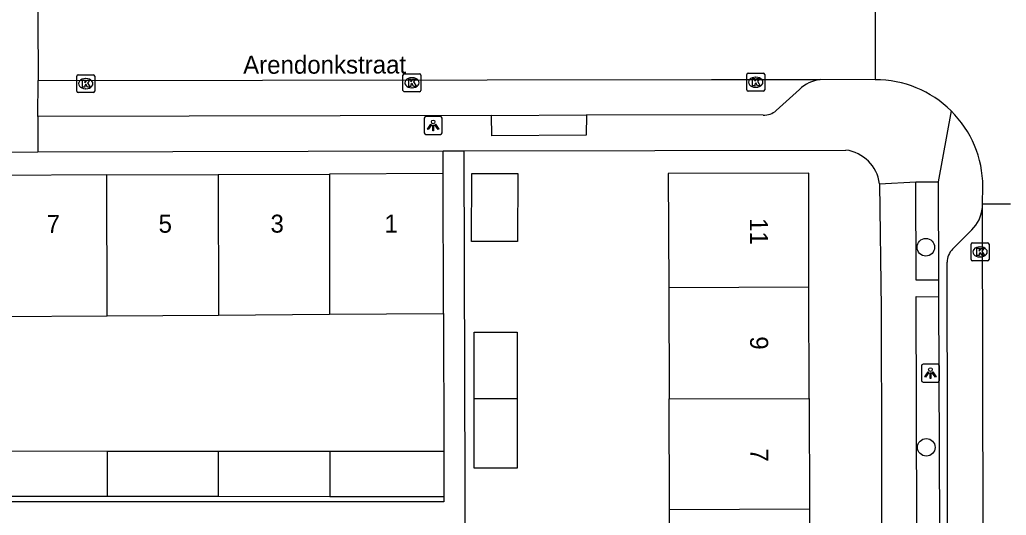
# Model space of a CAD drawing. Extents: x 160732 to 162105, y 387428 to 388479.
# Drawn here: x 161247.5 to 161302.4, y 387840.8 to 387868.4 of the extents above; entities that cross this region are included whole.
import ezdxf

# ---------------------------------------------------------------- set-up
doc = ezdxf.new("R2010")
doc.units = 0
for name, color, linetype in [('IMGEO_Boom', 7, 'Continuous'), ('IMGEO_Kolk', 7, 'Continuous'), ('IMGEO_Lichtpunt', 7, 'Continuous'), ('IMGEO_Openbare_ruimte_label', 7, 'Continuous'), ('IMGEO_Pand', 7, 'Continuous'), ('IMGEO_Pand_nummerreeks', 7, 'Continuous'), ('IMGEO_Rijbaan_lokaal_gesloten', 7, 'Continuous'), ('IMGEO_Rijbaan_lokaal_open', 7, 'Continuous'), ('IMGEO_Voetpad_open', 7, 'Continuous')]:
    doc.layers.add(name, color=color, linetype=linetype)

msp = doc.modelspace()

# ---------------------------------------------------------------- linework, layer by layer
at = {"layer": 'IMGEO_Boom'}
for centre in [(161297.937, 387855.714), (161297.961, 387844.569)]:
    msp.add_circle(centre, 0.489, dxfattribs=at)
at = {"layer": 'IMGEO_Kolk'}
for p, q in [((161250.701, 387864.399), (161250.701, 387865.251)), ((161250.776, 387865.325), (161251.628, 387865.325)), ((161251.702, 387865.251), (161251.702, 387864.399)), ((161268.851, 387864.45), (161268.851, 387865.302)), ((161268.926, 387865.376), (161269.778, 387865.376)), ((161269.852, 387865.302), (161269.852, 387864.45)), ((161287.973, 387864.48), (161287.973, 387865.332)), ((161288.048, 387865.406), (161288.9, 387865.406)), ((161288.974, 387865.332), (161288.974, 387864.48)), ((161251.189, 387865.105), (161251.214, 387865.105)), ((161269.339, 387865.156), (161269.364, 387865.156)), ((161288.461, 387865.186), (161288.486, 387865.186)), ((161251.628, 387864.325), (161250.776, 387864.325)), ((161251.212, 387864.545), (161251.187, 387864.545)), ((161269.778, 387864.376), (161268.926, 387864.376)), ((161269.362, 387864.596), (161269.337, 387864.596)), ((161288.9, 387864.406), (161288.048, 387864.406)), ((161288.484, 387864.626), (161288.459, 387864.626)), ((161300.527, 387855.954), (161301.379, 387855.954)), ((161300.452, 387855.028), (161300.452, 387855.88)), ((161300.94, 387855.734), (161300.965, 387855.734)), ((161301.453, 387855.88), (161301.453, 387855.028)), ((161301.379, 387854.954), (161300.527, 387854.954)), ((161300.963, 387855.174), (161300.938, 387855.174))]:
    msp.add_line(p, q, dxfattribs=at)
for points in [[(161250.701, 387864.399), (161250.701, 387865.251)], [(161250.776, 387865.325), (161251.628, 387865.325)], [(161251.702, 387865.251), (161251.702, 387864.399)], [(161268.851, 387864.45), (161268.851, 387865.302)], [(161268.926, 387865.376), (161269.778, 387865.376)], [(161269.852, 387865.302), (161269.852, 387864.45)], [(161287.973, 387864.48), (161287.973, 387865.332)], [(161288.048, 387865.406), (161288.9, 387865.406)], [(161288.974, 387865.332), (161288.974, 387864.48)], [(161251.022, 387865.025), (161251.145, 387865.025), (161251.145, 387864.874), (161251.275, 387865.025), (161251.439, 387865.025), (161251.293, 387864.874), (161251.446, 387864.625), (161251.294, 387864.625), (161251.209, 387864.789), (161251.145, 387864.722), (161251.145, 387864.625), (161251.022, 387864.625), (161251.022, 387865.025)], [(161269.172, 387865.076), (161269.295, 387865.076), (161269.295, 387864.925), (161269.425, 387865.076), (161269.589, 387865.076), (161269.443, 387864.925), (161269.596, 387864.676), (161269.444, 387864.676), (161269.359, 387864.84), (161269.295, 387864.773), (161269.295, 387864.676), (161269.172, 387864.676), (161269.172, 387865.076)], [(161288.294, 387865.106), (161288.417, 387865.106), (161288.417, 387864.955), (161288.547, 387865.106), (161288.711, 387865.106), (161288.565, 387864.955), (161288.718, 387864.706), (161288.566, 387864.706), (161288.481, 387864.87), (161288.417, 387864.803), (161288.417, 387864.706), (161288.294, 387864.706), (161288.294, 387865.106)], [(161251.628, 387864.325), (161250.776, 387864.325)], [(161269.778, 387864.376), (161268.926, 387864.376)], [(161288.9, 387864.406), (161288.048, 387864.406)], [(161300.527, 387855.954), (161301.379, 387855.954)], [(161300.452, 387855.028), (161300.452, 387855.88)], [(161300.773, 387855.654), (161300.896, 387855.654), (161300.896, 387855.503), (161301.026, 387855.654), (161301.19, 387855.654), (161301.044, 387855.503), (161301.197, 387855.254), (161301.045, 387855.254), (161300.96, 387855.418), (161300.896, 387855.351), (161300.896, 387855.254), (161300.773, 387855.254), (161300.773, 387855.654)], [(161301.453, 387855.88), (161301.453, 387855.028)], [(161301.379, 387854.954), (161300.527, 387854.954)]]:
    msp.add_lwpolyline(points, dxfattribs=at)
for centre, start, end in [((161250.778, 387865.249), 91.552, 178.448), ((161250.778, 387865.249), 91.552, 178.448), ((161251.626, 387865.249), 1.552, 88.448), ((161251.626, 387865.249), 1.552, 88.448), ((161268.928, 387865.3), 91.552, 178.448), ((161268.928, 387865.3), 91.552, 178.448), ((161269.776, 387865.3), 1.552, 88.448), ((161269.776, 387865.3), 1.552, 88.448), ((161288.05, 387865.33), 91.552, 178.448), ((161288.05, 387865.33), 91.552, 178.448), ((161288.898, 387865.33), 1.552, 88.448), ((161288.898, 387865.33), 1.552, 88.448), ((161250.778, 387864.401), 181.552, 268.448), ((161250.778, 387864.401), 181.552, 268.448), ((161251.626, 387864.401), 271.552, 358.448), ((161251.626, 387864.401), 271.552, 358.448), ((161268.928, 387864.452), 181.552, 268.448), ((161268.928, 387864.452), 181.552, 268.448), ((161269.776, 387864.452), 271.552, 358.448), ((161269.776, 387864.452), 271.552, 358.448), ((161288.05, 387864.482), 181.552, 268.448), ((161288.05, 387864.482), 181.552, 268.448), ((161288.898, 387864.482), 271.552, 358.448), ((161288.898, 387864.482), 271.552, 358.448), ((161300.529, 387855.878), 91.552, 178.448), ((161300.529, 387855.878), 91.552, 178.448), ((161301.377, 387855.878), 1.552, 88.448), ((161301.377, 387855.878), 1.552, 88.448), ((161300.529, 387855.03), 181.552, 268.448), ((161300.529, 387855.03), 181.552, 268.448), ((161301.377, 387855.03), 271.552, 358.448), ((161301.377, 387855.03), 271.552, 358.448)]:
    msp.add_arc(centre, 0.0765, start, end, dxfattribs=at)
for centre, major_axis, ratio, start_param, end_param in [((161251.188, 387864.825), (-0.387, 0.002), 0.722429, 4.712389, 7.853982), ((161251.213, 387864.825), (-0.39, 0.002), 0.717154, 1.570796, 4.712389), ((161269.338, 387864.876), (-0.387, 0.002), 0.722429, 4.712389, 7.853982), ((161269.363, 387864.876), (-0.39, 0.002), 0.717154, 1.570796, 4.712389), ((161288.46, 387864.906), (-0.387, 0.002), 0.722429, 4.712389, 7.853982), ((161288.485, 387864.906), (-0.39, 0.002), 0.717154, 1.570796, 4.712389), ((161300.939, 387855.454), (-0.387, 0.002), 0.722429, 4.712389, 7.853982), ((161300.964, 387855.454), (-0.39, 0.002), 0.717154, 1.570796, 4.712389)]:
    msp.add_ellipse(centre, major_axis=major_axis, ratio=ratio, start_param=start_param, end_param=end_param, dxfattribs=at)
at = {"layer": 'IMGEO_Lichtpunt'}
for p, q in [((161270.034, 387862.898), (161270.034, 387862.091)), ((161270.034, 387862.898), (161270.034, 387862.091)), ((161270.936, 387862.993), (161270.128, 387862.993)), ((161270.936, 387862.993), (161270.128, 387862.993)), ((161271.03, 387862.091), (161271.03, 387862.898)), ((161271.03, 387862.091), (161271.03, 387862.898)), ((161270.128, 387861.997), (161270.936, 387861.997)), ((161270.128, 387861.997), (161270.936, 387861.997)), ((161297.694, 387849.103), (161297.694, 387848.296)), ((161297.694, 387849.103), (161297.694, 387848.296)), ((161298.596, 387849.198), (161297.788, 387849.198)), ((161298.596, 387849.198), (161297.788, 387849.198)), ((161298.69, 387848.296), (161298.69, 387849.103)), ((161298.69, 387848.296), (161298.69, 387849.103)), ((161297.788, 387848.202), (161298.596, 387848.202)), ((161297.788, 387848.202), (161298.596, 387848.202))]:
    msp.add_line(p, q, dxfattribs=at)
for points in [[(161270.408, 387862.562), (161270.447, 387862.534), (161270.259, 387862.272), (161270.221, 387862.299), (161270.408, 387862.562)], [(161270.51, 387862.514), (161270.557, 387862.514), (161270.557, 387862.192), (161270.51, 387862.192), (161270.51, 387862.514)], [(161270.62, 387862.534), (161270.658, 387862.561), (161270.845, 387862.299), (161270.806, 387862.271), (161270.62, 387862.534)], [(161298.068, 387848.767), (161298.107, 387848.739), (161297.919, 387848.477), (161297.881, 387848.504), (161298.068, 387848.767)], [(161298.28, 387848.739), (161298.318, 387848.766), (161298.505, 387848.504), (161298.466, 387848.476), (161298.28, 387848.739)], [(161298.17, 387848.719), (161298.217, 387848.719), (161298.217, 387848.397), (161298.17, 387848.397), (161298.17, 387848.719)]]:
    msp.add_lwpolyline(points, dxfattribs=at)
for centre in [(161270.533, 387862.696), (161298.193, 387848.901)]:
    msp.add_circle(centre, 0.0994, dxfattribs=at)
for centre, start, end in [((161270.128, 387862.898), 90, 180), ((161270.128, 387862.898), 90, 180), ((161270.936, 387862.898), 0, 90), ((161270.936, 387862.898), 0, 90), ((161270.128, 387862.091), 180, 270), ((161270.128, 387862.091), 180, 270), ((161270.936, 387862.091), 270, 0), ((161270.936, 387862.091), 270, 360), ((161297.788, 387849.103), 90, 180), ((161297.788, 387849.103), 90, 180), ((161298.596, 387849.103), 0, 90), ((161298.596, 387849.103), 0, 90), ((161297.788, 387848.296), 180, 270), ((161297.788, 387848.296), 180, 270), ((161298.596, 387848.296), 270, 0), ((161298.596, 387848.296), 270, 360)]:
    msp.add_arc(centre, 0.0946, start, end, dxfattribs=at)
at = {"layer": 'IMGEO_Pand'}
for points in [[(161252.383, 387859.743), (161246.192, 387859.719)], [(161252.383, 387859.743), (161258.574, 387859.768)], [(161252.392, 387851.899), (161252.383, 387859.743)], [(161258.574, 387859.768), (161264.765, 387859.792)], [(161258.574, 387859.768), (161258.582, 387851.94)], [(161271.094, 387859.817), (161264.765, 387859.792)], [(161264.765, 387859.792), (161264.773, 387851.982)], [(161271.102, 387852.024), (161271.094, 387859.817)], [(161272.663, 387856.039), (161272.677, 387859.823), (161275.24, 387859.814), (161275.226, 387856.03), (161272.663, 387856.039)], [(161291.437, 387853.482), (161291.422, 387859.849), (161283.61, 387859.821), (161283.633, 387853.456)], [(161291.437, 387853.482), (161283.633, 387853.456)], [(161283.633, 387853.456), (161283.655, 387847.277)], [(161291.452, 387847.288), (161291.437, 387853.482)], [(161246.201, 387851.857), (161252.392, 387851.899)], [(161252.392, 387851.899), (161258.582, 387851.94)], [(161258.582, 387851.94), (161264.773, 387851.982)], [(161264.773, 387851.982), (161271.102, 387852.024)], [(161272.813, 387847.262), (161272.813, 387850.976), (161275.206, 387850.976), (161275.206, 387847.265)], [(161275.206, 387847.265), (161272.813, 387847.262)], [(161275.206, 387847.265), (161275.206, 387843.408), (161272.813, 387843.408), (161272.813, 387847.262)], [(161283.655, 387847.277), (161291.452, 387847.288)], [(161283.677, 387841.098), (161283.655, 387847.277)], [(161291.452, 387847.288), (161291.466, 387841.125)], [(161252.401, 387844.347), (161246.21, 387844.35)], [(161252.401, 387844.347), (161252.404, 387841.843)], [(161258.59, 387844.345), (161252.401, 387844.347)], [(161264.781, 387844.342), (161258.59, 387844.345)], [(161258.592, 387841.841), (161258.59, 387844.345)], [(161271.125, 387844.34), (161264.781, 387844.342)], [(161264.781, 387844.342), (161264.783, 387841.838)], [(161271.125, 387844.34), (161271.124, 387841.836)], [(161246.213, 387841.846), (161252.404, 387841.843)], [(161252.404, 387841.843), (161258.592, 387841.841)], [(161258.592, 387841.841), (161264.783, 387841.838)], [(161264.783, 387841.838), (161271.124, 387841.836)], [(161291.466, 387841.125), (161283.677, 387841.098)], [(161283.7, 387834.918), (161283.677, 387841.098)], [(161291.466, 387841.125), (161291.481, 387834.947)]]:
    msp.add_lwpolyline(points, dxfattribs=at)
at = {"layer": 'IMGEO_Rijbaan_lokaal_gesloten'}
for points in [[(161301.086, 387857.923), (161301.09, 387858.133)], [(161301.09, 387858.133), (161302.515, 387858.13), (161302.653, 387858.13)], [(161301.167, 387821.661), (161301.086, 387857.923)]]:
    msp.add_lwpolyline(points, dxfattribs=at)
at = {"layer": 'IMGEO_Rijbaan_lokaal_open'}
for points in [[(161248.506, 387875.48), (161248.554, 387864.996)], [(161295.125, 387870.107), (161295.122, 387865.04)], [(161248.554, 387864.996), (161286.018, 387865.061), (161292.052, 387865.05)], [(161295.122, 387865.04), (161292.052, 387865.05)], [(161301.09, 387858.133), (161301.111, 387859.101)]]:
    msp.add_lwpolyline(points, dxfattribs=at)
for centre, radius, start, end in [((161295.14, 387859.068), 5.972, 45.2459, 90.1768), ((161295.14, 387859.07), 5.971, 0.3014, 45.2319)]:
    msp.add_arc(centre, radius, start, end, dxfattribs=at)
at = {"layer": 'IMGEO_Voetpad_open'}
for points in [[(161248.537, 387862.996), (161248.554, 387864.996)], [(161290.906, 387864.497), (161289.612, 387863.323)], [(161273.782, 387863.048), (161248.537, 387862.996)], [(161273.782, 387863.048), (161279.053, 387863.08)], [(161279.053, 387863.08), (161279.046, 387861.955), (161273.795, 387861.926), (161273.782, 387863.048)], [(161288.889, 387863.075), (161279.053, 387863.08)], [(161299.345, 387863.309), (161298.619, 387859.359)], [(161248.537, 387862.996), (161248.537, 387861.034)], [(161222.59, 387860.981), (161248.537, 387861.034)], [(161248.537, 387861.034), (161271.091, 387861.08)], [(161271.091, 387861.08), (161272.24, 387861.082)], [(161271.094, 387859.817), (161271.091, 387861.08)], [(161272.24, 387861.082), (161293.49, 387861.125)], [(161272.24, 387861.082), (161272.36, 387817.267)], [(161295.361, 387859.255), (161297.376, 387859.353)], [(161295.361, 387859.255), (161295.458, 387852.3), (161295.533, 387819.333)], [(161297.376, 387859.353), (161298.619, 387859.359)], [(161298.645, 387853.88), (161297.402, 387853.874), (161297.376, 387859.353)], [(161298.619, 387859.359), (161298.645, 387853.88)], [(161299.427, 387855.615), (161300.494, 387856.68)], [(161299.188, 387824.784), (161299.122, 387854.876)], [(161298.645, 387853.88), (161298.644, 387852.961)], [(161298.689, 387840.088), (161297.432, 387840.097), (161297.403, 387852.969), (161298.644, 387852.961)], [(161298.644, 387852.961), (161298.689, 387840.088)], [(161271.102, 387852.024), (161271.125, 387844.34)], [(161271.124, 387841.836), (161271.124, 387841.531), (161221.255, 387841.531)]]:
    msp.add_lwpolyline(points, dxfattribs=at)
for centre, radius, start, end in [((161292.304, 387863.064), 2.002, 97.2333, 134.2858), ((161288.937, 387864.112), 1.038, 267.3362, 310.5293), ((161293.203, 387858.967), 2.177, 7.5949, 82.4357), ((161299.07, 387858.121), 2.026, 314.6668, 354.3994), ((161300.177, 387854.873), 1.055, 135.3101, 179.8361)]:
    msp.add_arc(centre, radius, start, end, dxfattribs=at)

# ---------------------------------------------------------------- texts
at = {"layer": 'IMGEO_Openbare_ruimte_label'}
msp.add_text('Arendonkstraat', height=1, rotation=0.1146, dxfattribs=at).set_placement((161259.96, 387865.374))
at = {"layer": 'IMGEO_Pand_nummerreeks'}
for s, rotation, p in [('3', 0.0564, (161261.482, 387856.528)), ('1', 0.0564, (161267.823, 387856.534)), ('7', 0.0564, (161249.029, 387856.516)), ('5', 0.0564, (161255.256, 387856.522)), ('11', 270.1346, (161288.147, 387857.341)), ('9', 270.1346, (161288.164, 387850.752)), ('7', 270.1346, (161288.179, 387844.51))]:
    msp.add_text(s, height=1, rotation=rotation, dxfattribs=at).set_placement(p)

doc.saveas('drawing.dxf')
